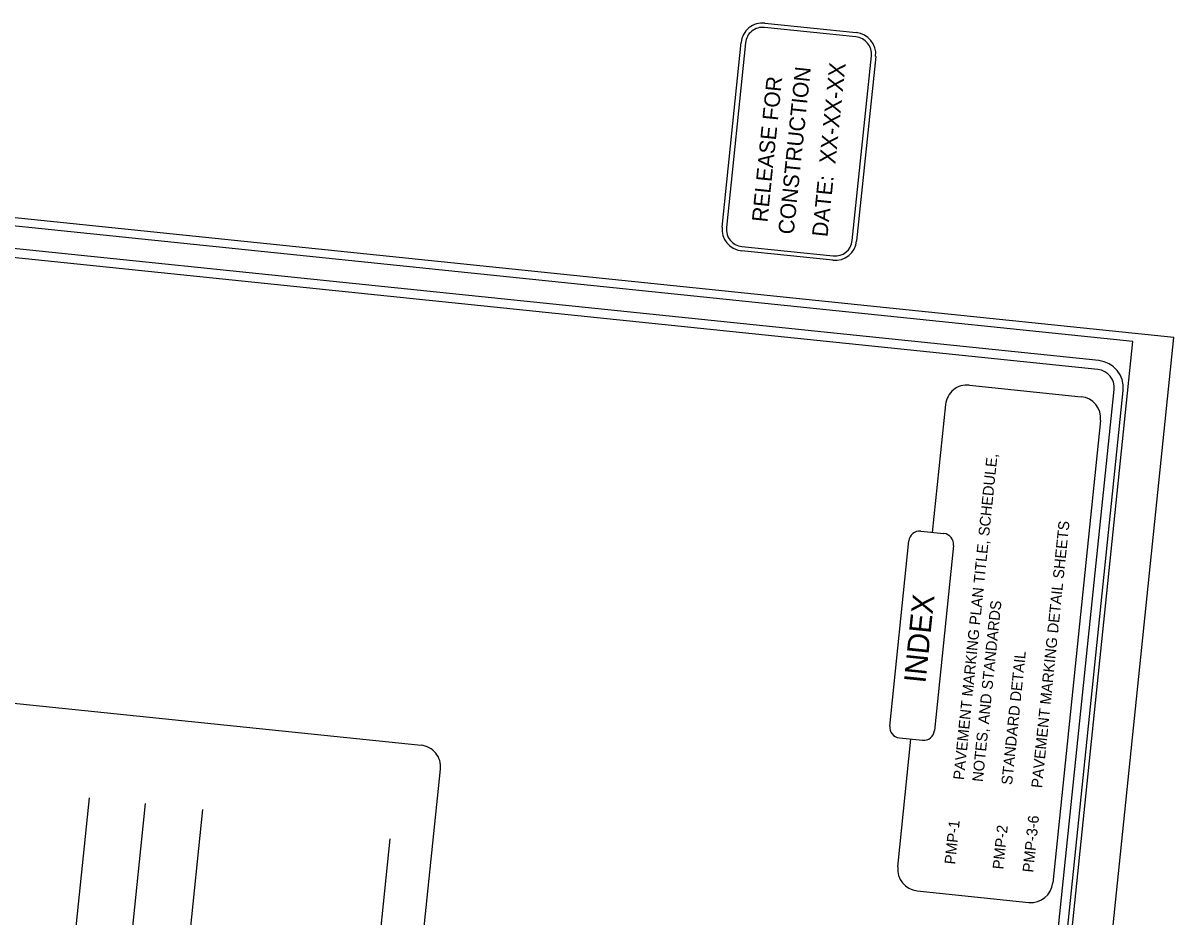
# Model space of a CAD drawing. Extents: x 2077770 to 2079037, y 247476 to 249877.
# Drawn here: x 2078401 to 2079037, y 249383 to 249877 of the extents above; entities that cross this region are included whole.
import ezdxf

# ---------------------------------------------------------------- set-up
doc = ezdxf.new("R2010")
doc.units = 0
for name, color, linetype in [('Default', 7, 'Continuous'), ('Prop DSN Text', 7, 'Continuous'), ('Sheet Block Title CELL', 7, 'Continuous'), ('Sheet Plot Border Inside CELL', 7, 'Continuous'), ('Sheet Plot Border Outside CELL', 7, 'Continuous'), ('Sheet Title CELL', 7, 'Continuous')]:
    doc.layers.add(name, color=color, linetype=linetype)

msp = doc.modelspace()

# ---------------------------------------------------------------- linework, layer by layer
at = {"layer": 'Default'}
for p, q in [((2078405.9, 249140.03), (2078437.76, 249448.7)), ((2078437.01, 249136.79), (2078468.87, 249445.46)), ((2078468.6, 249133.53), (2078500.46, 249442.19)), ((2078572.22, 249117.41), (2078604.08, 249426.08))]:
    msp.add_line(p, q, dxfattribs=at)
at = {"layer": 'Sheet Block Title CELL'}
for p, q in [((2078861.53, 249869.56), (2078811.01, 249874.77)), ((2078811.25, 249877.16), (2078861.78, 249871.95)), ((2078787.55, 249764.38), (2078798.09, 249866.46)), ((2078800.47, 249866.21), (2078789.94, 249764.13)), ((2078859.56, 249756.95), (2078870.09, 249859.03)), ((2078872.48, 249858.78), (2078861.95, 249756.7)), ((2078798.5, 249753.6), (2078849.02, 249748.38)), ((2078848.78, 249745.99), (2078798.25, 249751.21))]:
    msp.add_line(p, q, dxfattribs=at)
for centre, radius, start, end in [((2078810.02, 249865.23), 12, 84.10721, 174.10721), ((2078810.02, 249865.23), 9.6, 84.10721, 174.10721), ((2078860.54, 249860.01), 9.6, 354.10721, 84.10721), ((2078860.54, 249860.01), 12, 354.10721, 84.10721), ((2078799.49, 249763.15), 12, 174.10721, 264.10721), ((2078799.49, 249763.15), 9.6, 174.10721, 264.10721), ((2078850.01, 249757.93), 12, 264.10721, 354.10721), ((2078850.01, 249757.93), 9.6, 264.10721, 354.10721)]:
    msp.add_arc(centre, radius, start, end, dxfattribs=at)
at = {"layer": 'Sheet Plot Border Inside CELL'}
msp.add_lwpolyline([(2078843.53, 248043.45), (2079014.62, 249701.14), (2077965.1, 249809.47), (2077794, 248151.77)], close=True, dxfattribs=at)
at = {"layer": 'Sheet Plot Border Outside CELL'}
msp.add_lwpolyline([(2077943.23, 249816.25), (2077770.34, 248141.15), (2078864.51, 248028.21), (2079037.4, 249703.31)], close=True, dxfattribs=at)
at = {"layer": 'Sheet Title CELL'}
for p, q in [((2078924.27, 249676.94), (2078986.08, 249670.55)), ((2078858.5, 248262.08), (2079004.29, 249674.56)), ((2078911.1, 249666.24), (2078903.8, 249595.52)), ((2078996.79, 249657.39), (2078970.38, 249401.58)), ((2078897.4, 249596.18), (2078910.19, 249594.86)), ((2078880.25, 249488.4), (2078890.82, 249590.82)), ((2078915.54, 249588.27), (2078904.97, 249485.85)), ((2078255.28, 249515.4), (2078621.17, 249477.81)), ((2078884.69, 249410.43), (2078891.99, 249481.15)), ((2078885.6, 249481.81), (2078898.39, 249480.49)), ((2078593.75, 249095.03), (2078631.89, 249464.62)), ((2078895.4, 249397.26), (2078957.21, 249390.87))]:
    msp.add_line(p, q, dxfattribs=at)
for points in [[(2078995.37, 249685.54), (2077980.76, 249790.26)], [(2078995.88, 249690.51), (2077981.27, 249795.23)], [(2078858.34, 248211.82), (2079009.26, 249674.05)]]:
    msp.add_lwpolyline(points, dxfattribs=at)
for centre, radius, start, end in [((2078994.34, 249675.59), 15, 354.10721, 84.10721), ((2078994.34, 249675.59), 10, 354.10721, 84.10721), ((2078923.03, 249665.01), 12, 84.10721, 174.10721), ((2078984.85, 249658.62), 12, 354.10721, 84.10721), ((2078896.79, 249590.21), 6, 84.10721, 174.10721), ((2078909.57, 249588.89), 6, 354.10721, 84.10721), ((2078886.22, 249487.78), 6, 174.10721, 264.10721), ((2078899, 249486.46), 6, 264.10721, 354.10721), ((2078619.95, 249465.86), 12, 354.10721, 84.16357), ((2078896.63, 249409.2), 12, 174.10721, 264.10721), ((2078958.45, 249402.81), 12, 264.10721, 354.10721)]:
    msp.add_arc(centre, radius, start, end, dxfattribs=at)

# ---------------------------------------------------------------- texts
at = {"layer": 'Prop DSN Text'}
for s, height, p in [('PAVEMENT MARKING PLAN TITLE, SCHEDULE,', 6, (2078921.29, 249458.37)), ('PAVEMENT MARKING DETAIL SHEETS', 6, (2078964.44, 249453.89)), ('INDEX', 12, (2078900, 249511.76)), ('NOTES, AND STANDARDS', 6, (2078931.73, 249457.29)), ('STANDARD DETAIL', 6, (2078947.88, 249455.6)), ('PMP-1', 6, (2078916.46, 249411.65)), ('PMP-3-6', 6, (2078959.61, 249407.18)), ('PMP-2', 6, (2078943.05, 249408.89))]:
    msp.add_text(s, height=height, rotation=84.10721, dxfattribs=at).set_placement(p)
at = {"layer": 'Sheet Block Title CELL'}
for s, height, p in [('XX-XX-XX', 9, (2078850.17, 249798.94)), ('RELEASE FOR', 8.6417, (2078812.6, 249766.77)), ('CONSTRUCTION', 8.6417, (2078827.11, 249760)), ('DATE:', 8.642, (2078845.83, 249758.64))]:
    msp.add_text(s, height=height, rotation=84.10721, dxfattribs=at).set_placement(p)

doc.saveas('drawing.dxf')
